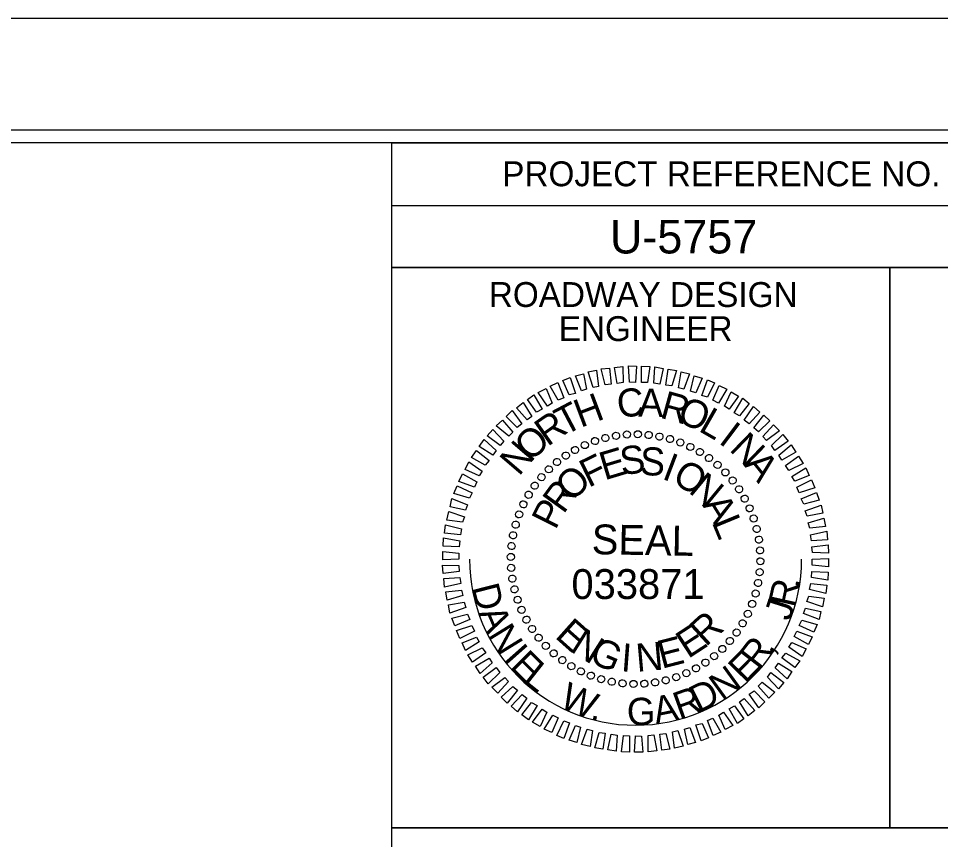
# Model space of a CAD drawing. Extents: x 957297 to 961629, y 830661 to 840840.
# Drawn here: x 960102.7 to 960288, y 831595.7 to 831760.7 of the extents above; entities that cross this region are included whole.
import ezdxf

# ---------------------------------------------------------------- set-up
doc = ezdxf.new("R2010")
doc.units = 0
for name, color, linetype in [('Scratch_Level_0', 7, 'Continuous'), ('Sheet Data Field CELL', 7, 'Continuous'), ('Sheet Plot Border Inside CELL', 7, 'Continuous'), ('Sheet Plot Border Outside CELL', 7, 'Continuous'), ('Sheet Professional Seal CELL', 7, 'Continuous'), ('Sheet Profile Grid Minor CELL', 7, 'Continuous'), ('Sheet Sticker Exception Certification CELL', 7, 'Continuous'), ('Sheet Typical CELL', 7, 'Continuous')]:
    doc.layers.add(name, color=color, linetype=linetype)

msp = doc.modelspace()

# ---------------------------------------------------------------- linework, layer by layer
at = {"layer": 'Scratch_Level_0'}
msp.add_arc((960226.74, 831652.06), 33.36, 180, 360, dxfattribs=at)
at = {"layer": 'Sheet Plot Border Inside CELL'}
msp.add_lwpolyline([(960390.3, 831738.21), (958723.8, 831738.21), (958723.8, 830683.11), (960390.3, 830683.11)], close=True, dxfattribs=at)
at = {"layer": 'Sheet Plot Border Outside CELL'}
msp.add_lwpolyline([(960394.8, 831760.66), (958710.8, 831760.66), (958710.8, 830660.66), (960394.8, 830660.66)], close=True, dxfattribs=at)
at = {"layer": 'Sheet Professional Seal CELL'}
for p, q in [((960224.99, 831677.11), (960224.99, 831677.11)), ((960227.19, 831677.16), (960227.19, 831677.16)), ((960218.54, 831675.81), (960218.54, 831675.81)), ((960220.64, 831676.41), (960220.64, 831676.41)), ((960222.84, 831676.81), (960222.84, 831676.81)), ((960229.39, 831677.01), (960229.39, 831677.01)), ((960231.54, 831676.66), (960231.54, 831676.66)), ((960233.64, 831676.21), (960233.64, 831676.21)), ((960235.74, 831675.51), (960235.74, 831675.51)), ((960214.59, 831674.01), (960214.59, 831674.01)), ((960216.54, 831675.01), (960216.54, 831675.01)), ((960237.74, 831674.61), (960237.74, 831674.61)), ((960239.69, 831673.61), (960239.69, 831673.61)), ((960210.94, 831671.61), (960210.94, 831671.61)), ((960212.69, 831672.86), (960212.69, 831672.86)), ((960241.49, 831672.36), (960241.49, 831672.36)), ((960209.29, 831670.11), (960209.29, 831670.11)), ((960243.24, 831671.01), (960243.24, 831671.01)), ((960207.79, 831668.56), (960207.79, 831668.56)), ((960244.79, 831669.51), (960244.79, 831669.51)), ((960246.29, 831667.86), (960246.29, 831667.86)), ((960206.44, 831666.81), (960206.44, 831666.81)), ((960247.54, 831666.11), (960247.54, 831666.11)), ((960205.19, 831665.01), (960205.19, 831665.01)), ((960248.69, 831664.21), (960248.69, 831664.21)), ((960204.19, 831663.06), (960204.19, 831663.06)), ((960203.29, 831661.06), (960203.29, 831661.06)), ((960249.69, 831662.26), (960249.69, 831662.26)), ((960202.59, 831658.96), (960202.59, 831658.96)), ((960250.49, 831660.26), (960250.49, 831660.26)), ((960202.14, 831656.86), (960202.14, 831656.86)), ((960251.09, 831658.16), (960251.09, 831658.16)), ((960251.49, 831655.96), (960251.49, 831655.96)), ((960201.79, 831654.71), (960201.79, 831654.71)), ((960251.79, 831653.81), (960251.79, 831653.81)), ((960201.64, 831652.51), (960201.64, 831652.51)), ((960226.74, 831652.06), (960226.74, 831652.06)), ((960251.84, 831651.61), (960251.84, 831651.61)), ((960201.69, 831650.31), (960201.69, 831650.31)), ((960251.69, 831649.41), (960251.69, 831649.41)), ((960201.99, 831648.16), (960201.99, 831648.16)), ((960202.39, 831645.96), (960202.39, 831645.96)), ((960251.34, 831647.26), (960251.34, 831647.26)), ((960202.99, 831643.86), (960202.99, 831643.86)), ((960250.89, 831645.16), (960250.89, 831645.16)), ((960250.19, 831643.06), (960250.19, 831643.06)), ((960203.79, 831641.86), (960203.79, 831641.86)), ((960249.29, 831641.06), (960249.29, 831641.06)), ((960204.79, 831639.91), (960204.79, 831639.91)), ((960248.29, 831639.11), (960248.29, 831639.11)), ((960205.94, 831638.01), (960205.94, 831638.01)), ((960247.04, 831637.31), (960247.04, 831637.31)), ((960207.19, 831636.26), (960207.19, 831636.26)), ((960208.69, 831634.61), (960208.69, 831634.61)), ((960245.69, 831635.56), (960245.69, 831635.56)), ((960210.24, 831633.11), (960210.24, 831633.11)), ((960244.19, 831634.01), (960244.19, 831634.01)), ((960211.99, 831631.76), (960211.99, 831631.76)), ((960240.79, 831631.26), (960240.79, 831631.26)), ((960242.54, 831632.51), (960242.54, 831632.51)), ((960213.79, 831630.51), (960213.79, 831630.51)), ((960215.74, 831629.51), (960215.74, 831629.51)), ((960236.94, 831629.11), (960236.94, 831629.11)), ((960238.89, 831630.11), (960238.89, 831630.11)), ((960217.74, 831628.61), (960217.74, 831628.61)), ((960219.84, 831627.91), (960219.84, 831627.91)), ((960221.94, 831627.46), (960221.94, 831627.46)), ((960224.09, 831627.11), (960224.09, 831627.11)), ((960230.64, 831627.31), (960230.64, 831627.31)), ((960232.84, 831627.71), (960232.84, 831627.71)), ((960234.94, 831628.31), (960234.94, 831628.31)), ((960226.29, 831626.96), (960226.29, 831626.96)), ((960228.49, 831627.01), (960228.49, 831627.01))]:
    msp.add_line(p, q, dxfattribs=at)
for points in [[(960220.64, 831687.06), (960219.84, 831690.26), (960221.49, 831690.41), (960221.84, 831687.21)], [(960223.04, 831687.36), (960222.49, 831690.56), (960224.19, 831690.76), (960224.24, 831687.51)], [(960225.54, 831687.61), (960225.29, 831690.86), (960226.94, 831690.81), (960226.74, 831687.56)], [(960227.94, 831687.56), (960227.94, 831690.81), (960229.59, 831690.76), (960229.14, 831687.51)], [(960230.44, 831687.41), (960230.64, 831690.66), (960232.29, 831690.36), (960231.64, 831687.21)], [(960232.84, 831687.01), (960233.29, 831690.21), (960234.94, 831689.96), (960234.04, 831686.86)], [(960213.39, 831685.06), (960212.09, 831687.96), (960213.59, 831688.56), (960214.64, 831685.36)], [(960215.84, 831685.86), (960214.69, 831688.86), (960216.24, 831689.31), (960216.89, 831686.21)], [(960218.24, 831686.51), (960217.19, 831689.66), (960218.89, 831690.01), (960219.29, 831686.76)], [(960235.39, 831686.46), (960235.89, 831689.71), (960237.59, 831689.31), (960236.44, 831686.21)], [(960237.79, 831685.81), (960238.54, 831688.91), (960240.09, 831688.41), (960238.84, 831685.46)], [(960211.19, 831684.01), (960209.59, 831686.81), (960211.14, 831687.51), (960212.29, 831684.46)], [(960240.04, 831684.91), (960241.19, 831688.06), (960242.59, 831687.46), (960241.19, 831684.56)], [(960242.29, 831683.96), (960243.54, 831686.91), (960245.09, 831686.21), (960243.39, 831683.41)], [(960206.84, 831681.56), (960204.99, 831684.11), (960206.29, 831685.06), (960207.94, 831682.16)], [(960209.04, 831682.81), (960207.19, 831685.51), (960208.74, 831686.31), (960209.99, 831683.41)], [(960244.59, 831682.81), (960245.94, 831685.66), (960247.44, 831684.81), (960245.54, 831682.21)], [(960204.94, 831680.06), (960202.79, 831682.46), (960204.14, 831683.51), (960205.89, 831680.71)], [(960246.54, 831681.46), (960248.29, 831684.36), (960249.59, 831683.31), (960247.64, 831680.86)], [(960248.59, 831679.96), (960250.44, 831682.71), (960251.74, 831681.61), (960249.54, 831679.26)], [(960202.94, 831678.51), (960200.74, 831680.71), (960201.94, 831681.91), (960203.89, 831679.21)], [(960250.49, 831678.41), (960252.54, 831681.01), (960253.74, 831679.81), (960251.44, 831677.66)], [(960201.29, 831676.76), (960198.74, 831678.81), (960199.99, 831679.96), (960202.09, 831677.56)], [(960252.29, 831676.66), (960254.44, 831679.01), (960255.64, 831677.81), (960253.04, 831675.86)], [(960199.54, 831674.86), (960196.94, 831676.81), (960198.04, 831678.11), (960200.24, 831675.76)], [(960254.04, 831674.86), (960256.34, 831677.11), (960257.39, 831675.76), (960254.74, 831673.86)], [(960198.04, 831672.96), (960195.34, 831674.66), (960196.29, 831676.11), (960198.69, 831673.91)], [(960196.54, 831670.96), (960193.74, 831672.46), (960194.74, 831673.86), (960197.34, 831671.86)], [(960255.54, 831672.91), (960257.99, 831675.01), (960258.94, 831673.56), (960256.14, 831671.96)], [(960195.34, 831668.81), (960192.49, 831670.06), (960193.24, 831671.61), (960195.94, 831669.76)], [(960256.84, 831670.86), (960259.49, 831672.76), (960260.44, 831671.26), (960257.54, 831669.86)], [(960258.14, 831668.66), (960260.94, 831670.41), (960261.59, 831668.86), (960258.74, 831667.71)], [(960194.34, 831666.51), (960191.24, 831667.66), (960191.99, 831669.21), (960194.84, 831667.61)], [(960259.14, 831666.51), (960262.09, 831668.01), (960262.74, 831666.41), (960259.64, 831665.41)], [(960193.34, 831664.31), (960190.24, 831665.21), (960190.89, 831666.76), (960193.89, 831665.36)], [(960192.59, 831661.91), (960189.49, 831662.56), (960189.84, 831664.21), (960192.99, 831662.96)], [(960260.04, 831664.16), (960263.09, 831665.46), (960263.64, 831663.91), (960260.54, 831663.11)], [(960260.84, 831661.76), (960264.04, 831662.91), (960264.34, 831661.26), (960261.19, 831660.71)], [(960191.94, 831659.51), (960188.84, 831659.91), (960189.19, 831661.61), (960192.34, 831660.56)], [(960191.54, 831656.96), (960188.34, 831657.26), (960188.54, 831658.96), (960191.79, 831658.16)], [(960261.44, 831659.36), (960264.59, 831660.31), (960264.89, 831658.61), (960261.74, 831658.31)], [(960261.89, 831656.96), (960265.14, 831657.66), (960265.29, 831655.96), (960262.09, 831655.76)], [(960191.29, 831654.56), (960188.04, 831654.66), (960188.14, 831656.31), (960191.39, 831655.76)], [(960262.19, 831654.56), (960265.44, 831654.96), (960265.54, 831653.26), (960262.29, 831653.36)], [(960191.24, 831652.06), (960187.99, 831651.91), (960187.99, 831653.61), (960191.24, 831653.26)], [(960262.24, 831652.06), (960265.49, 831652.21), (960265.49, 831650.51), (960262.24, 831650.86)], [(960191.29, 831649.56), (960188.04, 831649.16), (960187.94, 831650.86), (960191.19, 831650.76)], [(960262.19, 831649.56), (960265.44, 831649.46), (960265.34, 831647.81), (960262.09, 831648.36)], [(960191.59, 831647.16), (960188.34, 831646.46), (960188.19, 831648.16), (960191.39, 831648.36)], [(960192.04, 831644.76), (960188.89, 831643.81), (960188.59, 831645.51), (960191.74, 831645.81)], [(960261.94, 831647.16), (960265.14, 831646.86), (960264.94, 831645.16), (960261.69, 831645.96)], [(960261.54, 831644.61), (960264.64, 831644.21), (960264.29, 831642.51), (960261.14, 831643.56)], [(960192.64, 831642.36), (960189.44, 831641.21), (960189.14, 831642.86), (960192.29, 831643.41)], [(960260.89, 831642.21), (960263.99, 831641.56), (960263.64, 831639.91), (960260.49, 831641.16)], [(960193.44, 831639.96), (960190.39, 831638.66), (960189.84, 831640.21), (960192.94, 831641.01)], [(960194.34, 831637.61), (960191.39, 831636.11), (960190.74, 831637.71), (960193.84, 831638.71)], [(960260.14, 831639.81), (960263.24, 831638.91), (960262.59, 831637.36), (960259.59, 831638.76)], [(960195.34, 831635.46), (960192.54, 831633.71), (960191.89, 831635.26), (960194.74, 831636.41)], [(960259.14, 831637.61), (960262.24, 831636.46), (960261.49, 831634.91), (960258.64, 831636.51)], [(960258.14, 831635.31), (960260.99, 831634.06), (960260.24, 831632.51), (960257.54, 831634.36)], [(960196.64, 831633.26), (960193.99, 831631.36), (960193.04, 831632.86), (960195.94, 831634.26)], [(960256.94, 831633.16), (960259.74, 831631.66), (960258.74, 831630.26), (960256.14, 831632.26)], [(960197.94, 831631.21), (960195.49, 831629.11), (960194.54, 831630.56), (960197.34, 831632.16)], [(960255.44, 831631.16), (960258.14, 831629.46), (960257.19, 831628.01), (960254.79, 831630.21)], [(960199.44, 831629.26), (960197.14, 831627.01), (960196.09, 831628.36), (960198.74, 831630.26)], [(960253.94, 831629.26), (960256.54, 831627.31), (960255.44, 831626.01), (960253.24, 831628.36)], [(960201.19, 831627.46), (960199.04, 831625.11), (960197.84, 831626.31), (960200.44, 831628.26)], [(960252.19, 831627.36), (960254.74, 831625.31), (960253.49, 831624.16), (960251.39, 831626.56)], [(960202.99, 831625.71), (960200.94, 831623.11), (960199.74, 831624.31), (960202.04, 831626.46)], [(960250.54, 831625.61), (960252.74, 831623.41), (960251.54, 831622.21), (960249.59, 831624.91)], [(960204.89, 831624.16), (960203.04, 831621.41), (960201.74, 831622.51), (960203.94, 831624.86)], [(960248.54, 831624.06), (960250.69, 831621.66), (960249.34, 831620.61), (960247.59, 831623.41)], [(960206.94, 831622.66), (960205.19, 831619.76), (960203.89, 831620.81), (960205.84, 831623.26)], [(960208.89, 831621.31), (960207.54, 831618.46), (960206.04, 831619.31), (960207.94, 831621.91)], [(960246.64, 831622.56), (960248.49, 831620.01), (960247.19, 831619.06), (960245.54, 831621.96)], [(960211.19, 831620.16), (960209.94, 831617.21), (960208.39, 831617.91), (960210.09, 831620.71)], [(960242.29, 831620.11), (960243.89, 831617.31), (960242.34, 831616.61), (960241.19, 831619.66)], [(960244.44, 831621.31), (960246.29, 831618.61), (960244.74, 831617.81), (960243.49, 831620.71)], [(960213.44, 831619.21), (960212.29, 831616.06), (960210.89, 831616.66), (960212.29, 831619.56)], [(960215.69, 831618.31), (960214.94, 831615.21), (960213.39, 831615.71), (960214.64, 831618.66)], [(960218.09, 831617.66), (960217.59, 831614.41), (960215.89, 831614.81), (960217.04, 831617.91)], [(960237.64, 831618.26), (960238.79, 831615.26), (960237.24, 831614.81), (960236.59, 831617.91)], [(960240.09, 831619.06), (960241.39, 831616.16), (960239.89, 831615.56), (960238.84, 831618.76)], [(960220.64, 831617.11), (960220.19, 831613.91), (960218.54, 831614.16), (960219.44, 831617.26)], [(960223.04, 831616.71), (960222.84, 831613.46), (960221.19, 831613.76), (960221.84, 831616.91)], [(960225.54, 831616.56), (960225.54, 831613.31), (960223.89, 831613.36), (960224.34, 831616.61)], [(960227.94, 831616.51), (960228.19, 831613.26), (960226.54, 831613.31), (960226.74, 831616.56)], [(960230.44, 831616.76), (960230.99, 831613.56), (960229.29, 831613.36), (960229.24, 831616.61)], [(960232.84, 831617.06), (960233.64, 831613.86), (960231.99, 831613.71), (960231.64, 831616.91)], [(960235.24, 831617.61), (960236.29, 831614.46), (960234.59, 831614.11), (960234.19, 831617.36)]]:
    msp.add_lwpolyline(points, close=True, dxfattribs=at)
for centre, major_axis in [((960220.68, 831676.4), (-0.174, 0.699)), ((960222.82, 831676.83), (-0.113, 0.711)), ((960224.99, 831677.08), (-0.05, 0.718)), ((960227.18, 831677.14), (0.013, 0.72)), ((960229.37, 831677), (0.075, 0.716)), ((960231.53, 831676.68), (0.137, 0.707)), ((960216.54, 831674.97), (-0.293, 0.658)), ((960218.58, 831675.78), (-0.234, 0.681)), ((960233.66, 831676.17), (0.198, 0.692)), ((960235.73, 831675.48), (0.258, 0.672)), ((960237.74, 831674.6), (0.316, 0.647)), ((960212.72, 831672.85), (-0.403, 0.597)), ((960214.58, 831674), (-0.349, 0.63)), ((960239.66, 831673.56), (0.371, 0.617)), ((960210.96, 831671.55), (-0.453, 0.56)), ((960241.49, 831672.35), (0.423, 0.582)), ((960243.2, 831670.99), (0.472, 0.543)), ((960209.32, 831670.1), (-0.5, 0.518)), ((960244.79, 831669.48), (0.518, 0.5)), ((960207.82, 831668.52), (-0.543, 0.472)), ((960246.23, 831667.85), (0.56, 0.453)), ((960206.45, 831666.8), (-0.582, 0.423)), ((960247.54, 831666.09), (0.597, 0.403)), ((960205.25, 831664.98), (-0.617, 0.371)), ((960248.68, 831664.22), (0.63, 0.349)), ((960204.2, 831663.06), (-0.647, 0.316)), ((960249.66, 831662.26), (0.658, 0.293)), ((960203.33, 831661.05), (-0.672, 0.258)), ((960250.46, 831660.23), (0.681, 0.234)), ((960202.64, 831658.97), (-0.692, 0.198)), ((960251.08, 831658.13), (0.699, 0.174)), ((960202.12, 831656.85), (-0.707, 0.137)), ((960251.52, 831655.99), (0.711, 0.113)), ((960201.8, 831654.68), (-0.716, 0.075)), ((960201.67, 831652.5), (-0.72, 0.013)), ((960251.76, 831653.81), (0.718, 0.05)), ((960251.82, 831651.62), (0.72, -0.013)), ((960201.73, 831650.31), (-0.718, -0.05)), ((960251.69, 831649.44), (0.716, -0.075)), ((960201.97, 831648.14), (-0.711, -0.113)), ((960251.36, 831647.28), (0.707, -0.137)), ((960202.41, 831645.99), (-0.699, -0.174)), ((960250.85, 831645.15), (0.692, -0.198)), ((960203.03, 831643.9), (-0.681, -0.234)), ((960250.16, 831643.07), (0.672, -0.258)), ((960203.83, 831641.86), (-0.658, -0.293)), ((960204.81, 831639.9), (-0.63, -0.349)), ((960249.29, 831641.07), (0.647, -0.316)), ((960205.95, 831638.04), (-0.597, -0.403)), ((960248.24, 831639.14), (0.617, -0.371)), ((960207.25, 831636.28), (-0.56, -0.453)), ((960245.67, 831635.61), (0.543, -0.472)), ((960247.03, 831637.32), (0.582, -0.423)), ((960208.7, 831634.64), (-0.518, -0.5)), ((960244.17, 831634.02), (0.5, -0.518)), ((960210.29, 831633.13), (-0.472, -0.543)), ((960242.53, 831632.57), (0.453, -0.56)), ((960212, 831631.77), (-0.423, -0.582)), ((960213.83, 831630.56), (-0.371, -0.617)), ((960238.9, 831630.13), (0.349, -0.63)), ((960240.77, 831631.27), (0.403, -0.597)), ((960215.75, 831629.52), (-0.316, -0.647)), ((960217.76, 831628.65), (-0.258, -0.672)), ((960234.91, 831628.35), (0.234, -0.681)), ((960236.94, 831629.15), (0.293, -0.658)), ((960219.83, 831627.95), (-0.198, -0.692)), ((960221.96, 831627.44), (-0.137, -0.707)), ((960224.12, 831627.12), (-0.075, -0.716)), ((960226.31, 831626.99), (-0.013, -0.72)), ((960228.49, 831627.04), (0.05, -0.718)), ((960230.67, 831627.29), (0.113, -0.711)), ((960232.81, 831627.73), (0.174, -0.699))]:
    msp.add_ellipse(centre, major_axis=major_axis, ratio=0.999708, dxfattribs=at)
at = {"layer": 'Sheet Sticker Exception Certification CELL'}
for p, q in [((960177.75, 831574.61), (960177.75, 831598.11)), ((960177.75, 831598.11), (960377.79, 831598.11))]:
    msp.add_line(p, q, dxfattribs=at)
at = {"layer": 'Sheet Typical CELL'}
for p, q in [((960177.75, 831723.11), (960377.8, 831723.11)), ((960277.8, 831710.61), (960277.8, 831598.16))]:
    msp.add_line(p, q, dxfattribs=at)
for points in [[(960377.8, 831735.66), (958877.8, 831735.66), (958877.8, 830685.66), (960377.8, 830685.66)], [(960177.75, 831735.66), (960377.8, 831735.66), (960377.8, 831710.61), (960177.75, 831710.61)], [(960177.75, 831710.61), (960277.8, 831710.61), (960277.8, 831598.11), (960177.75, 831598.11)], [(960277.8, 831710.61), (960377.8, 831710.61), (960377.8, 831598.11), (960277.8, 831598.11)]]:
    msp.add_lwpolyline(points, close=True, dxfattribs=at)

# ---------------------------------------------------------------- texts
at = {"layer": 'Sheet Data Field CELL'}
msp.add_text('U-5757', height=6.75, dxfattribs=at).set_placement((960221.59, 831713.46))
at = {"layer": 'Sheet Professional Seal CELL'}
for s, height, rotation, p in [('C', 5.64, 6.2199, (960223.29, 831680.41)), ('H', 5.64, 20.6195, (960215.69, 831678.41)), ('A', 5.64, 359.0203, (960227.24, 831680.71)), ('R', 5.64, 344.6211, (960231.44, 831680.51)), ('T', 5.64, 27.8198, (960212.44, 831676.76)), ('O', 5.64, 337.4212, (960234.79, 831679.76)), ('R', 5.64, 35.0205, (960209.04, 831674.56)), ('L', 5.64, 330.2209, (960239.19, 831677.91)), ('I', 5.64, 323.0201, (960243.24, 831675.51)), ('O', 5.64, 42.2217, (960205.59, 831671.46)), ('N', 5.64, 315.8189, (960245.39, 831673.96)), ('N', 5.64, 49.4235, (960203.29, 831668.56)), ('E', 5.64, 16.6111, (960220.49, 831667.86)), ('S', 5.64, 7.2556, (960223.94, 831668.91)), ('S', 5.64, 357.9004, (960227.54, 831668.96)), ('F', 5.64, 25.967, (960217.29, 831666.36)), ('I', 5.64, 339.1896, (960231.84, 831668.26)), ('O', 5.64, 329.8335, (960233.84, 831667.56)), ('A', 5.64, 308.6172, (960248.34, 831671.01)), ('O', 5.64, 44.6812, (960213.99, 831663.41)), ('N', 5.64, 320.4766, (960237.19, 831665.56)), ('R', 5.64, 54.0396, (960212.24, 831660.96)), ('P', 5.64, 63.3989, (960210.64, 831657.76)), ('A', 5.64, 301.7603, (960240.04, 831662.96)), ('L', 5.64, 292.4008, (960241.99, 831659.51)), ('SEAL', 5.998, 359, (960217.89, 831653.06)), ('E', 5.64, 318.2769, (960210.34, 831636.41)), ('R', 5.64, 42.4814, (960240.84, 831634.31)), ('E', 5.64, 33.1241, (960237.29, 831631.96)), ('N', 5.64, 327.634, (960213.34, 831633.71)), ('E', 5.64, 14.4118, (960231.99, 831630.01)), ('G', 5.64, 336.9902, (960217.14, 831631.46)), ('I', 5.64, 355.7012, (960223.69, 831629.56)), ('N', 5.64, 5.0564, (960227.04, 831629.41))]:
    msp.add_text(s, height=height, rotation=rotation, dxfattribs=at).set_placement(p)
at = {"layer": 'Sheet Profile Grid Minor CELL'}
for s, height, rotation, p in [('033871', 5.998, 360, (960213.85, 831644.05)), ('R', 5.5, 77.3541, (960258.72, 831642.16)), ('.', 5.5, 84.2805, (960259.68, 831646.09)), ('D', 5.5, 284.2682, (960193.75, 831646.42)), ('J', 5.5, 72.4855, (960257.76, 831639.48)), ('A', 5.5, 293.4128, (960195.07, 831641.25)), ('N', 5.5, 301.5986, (960196.93, 831636.85)), ('I', 5.5, 311.5304, (960200, 831631.93)), ('R', 5.5, 52.3788, (960251.55, 831629.59)), ('E', 5.5, 315.0508, (960201.29, 831630.33)), ('E', 5.5, 45.7958, (960248.8, 831626.89)), (',', 5.5, 59.3052, (960254.07, 831632.74)), ('L', 5.5, 321.6338, (960203.95, 831627.56)), ('N', 5.5, 35.8641, (960244.13, 831623.46)), ('W', 5.5, 336.8891, (960211.2, 831622.42)), ('D', 5.5, 26.7195, (960239.37, 831621.06)), ('R', 5.5, 19.793, (960235.54, 831619.77)), ('G', 5.5, 1.6755, (960225.06, 831618.63)), ('A', 5.5, 11.6072, (960230.85, 831618.84)), ('.', 5.5, 348.4952, (960217.48, 831619.9))]:
    msp.add_text(s, height=height, rotation=rotation, dxfattribs=at).set_placement(p)
at = {"layer": 'Sheet Typical CELL'}
for s, height, p in [('PROJECT REFERENCE NO.', 5.0001, (960199.95, 831726.96)), ('ROADWAY DESIGN', 5.0001, (960197.25, 831702.71)), ('ENGINEER', 5, (960211.3, 831695.86))]:
    msp.add_text(s, height=height, dxfattribs=at).set_placement(p)

doc.saveas('drawing.dxf')
